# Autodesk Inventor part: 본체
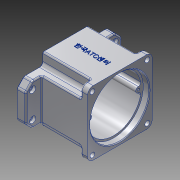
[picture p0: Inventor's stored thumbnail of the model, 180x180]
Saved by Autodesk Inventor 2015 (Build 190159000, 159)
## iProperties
Created: 2016-02
Part Number: 본체
Material: Aluminum 6061
Document SubType Name: Modeling
Designer: Administrator
Density: 2.7 g/cm^3
Appearance: Aluminum - Flat
Mass: 873.903 g
Surface Area: 763.799 cm^2
Volume: 323.668 cm^3
Author: Administrator
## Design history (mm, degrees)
sketch "Sketch1"
  geometry: L1 (60, 30)-(-60, 30); L2 (-70, 20)-(-70, -20); L3 (-60, -30)-(60, -30); L4 (70, -20)-(70, 20); L5 (70, 30)-(-70, -30); L6 (-70, 30)-(70, -30); L7 (60, 30)-(70, 20); L8 (60, -30)-(70, -20); L9 (-60, 30)-(-70, 20); L10 (-60, -30)-(-70, -20); 1 further point
  constraints: 20 end point, 8 point on line, 2 midpoint, 2 parallel, 1 horizontal, 1 perpendicular
  dimensions: "d0" = 140 distance of L6.end L5.end; "d1" = 60 distance of L5.end L6.start; "d2" = 10 distance of L1.start L5.start; "d3" = 10 distance of L4.end L5.start (= d2); "d4" = 10 distance of L3.end L6.end (= d2); "d5" = 10 distance of L4.start L6.end (= d4); "d6" = 10 distance of L1.end L6.start (= d2); "d7" = 10 distance of L2.start L6.start (= d6); "d8" = 10 distance of L3.start L5.end (= d2); "d9" = 10 distance of L2.end L5.end (= d8)
extrude "Extrusion1" new body sketch "Sketch1" distance "d10" = 13; taper "d11" = 0 deg
sketch "Sketch2"
  geometry: L1 (-19, -60)-(19, -60); L2 (19, -60)-(19, 60); L3 (19, 60)-(-19, 60); L4 (-19, 60)-(-19, -60); L5 (-19, -60)-(19, 60); L6 (19, -60)-(-19, 60); 5 further points
  constraints: 12 end point, 4 coincident, 2 midpoint, 2 parallel, 1 horizontal, 1 perpendicular
  dimensions: "d12" = 38 distance of L3.end L2.end; "d13" = 120 distance of L2.end L1.end
hole "Hole1" sketch "Sketch2" at (-19, -60), (19, -60), (19, 60), (-19, 60) diameter "d14" = 5; stored, may be unused: countersink angle "d18" = 90 deg, drill point angle "d20" = 0 deg; dims "d15" = 6.35, "d16" = 9, "d17" = 4, "d19" = 13
sketch "Sketch3"
  geometry: L1 (-47, -47)-(47, -47); L2 (47, -47)-(47, 47); L3 (47, 47)-(-47, 47); L4 (-47, 47)-(-47, -47); L5 (-47, -47)-(47, 47); L6 (47, -47)-(-47, 47); 1 further point
  constraints: 12 end point, 2 midpoint, 2 parallel, 1 horizontal, 1 perpendicular
  dimensions: "d21" = 94 distance of L3.end L2.end; "d22" = 94 distance of L2.end L1.end
extrude "Extrusion2" join sketch "Sketch3" distance "d23" = 67; taper "d24" = 0 deg
sketch "Sketch4"
  geometry: L1 (30, 33)-(47, 33); L2 (47, 33)-(47, 47); L3 (47, 47)-(30, 47); L4 (30, 47)-(30, 33); L5 (30, 33)-(47, 47); L6 (47, 33)-(30, 47); L7 (47, 47)-(47, -47) reference; L8 (30, 47)-(47, 47) reference; 2 further points
  constraints: 12 end point, 2 midpoint, 2 parallel, 1 collinear, 1 horizontal, 1 perpendicular
  dimensions: "d25" = 33 vertical distance of point (0, 0) L1.end; "d26" = 30 distance from line of L4 point (0, 0)
extrude "Extrusion3" cut sketch "Sketch4" distance "d27" = 57; taper "d28" = 0 deg
mirror "Mirror1"
mirror "Mirror2"
sketch "Sketch5"
  geometry: L1 (40, 40)-(-40, 40); L2 (-40, 40)-(-40, -40); L3 (-40, -40)-(40, -40); L4 (40, -40)-(40, 40); L5 (40, 40)-(-40, -40); L6 (-40, 40)-(40, -40); C1 r 3.5 at (-40, -40); C2 r 3.5 at (-40, 40); C3 r 3.5 at (40, 40); C4 r 3.5 at (40, -40); 1 further point
  constraints: 12 end point, 4 centre point, 4 coincident, 2 midpoint, 2 parallel, 1 horizontal, 1 perpendicular
  dimensions: "d29" = 80 distance of L3.end L2.end; "d30" = 80 distance of L2.end L1.end; "d31" = 7 diameter of C1; "d32" = 7 diameter of C2; "d33" = 7 diameter of C3; "d34" = 7 diameter of C4
extrude "Extrusion4" cut sketch "Sketch5" distance "d35" = 10; taper "d36" = 0 deg
sketch "Sketch6"
  geometry: L1 (30, -33)-(47, -33) reference; L2 (47, 33)-(47, -33) reference; L3 (47, 33)-(30, 33) reference; L4 (30, 33)-(30, -33) reference; L5 (-47, -33)-(-30, -33) reference; L6 (-30, -33)-(-30, 33) reference; L7 (-30, 33)-(-47, 33) reference; L8 (-47, -33)-(-47, 33) reference; 1 further point
extrude "Extrusion5" join sketch "Sketch6" distance "d37" = 13; taper "d38" = 0 deg
sketch "Sketch7"
  geometry: C1 r 28 at (11, 0); 1 further point
  constraints: 1 centre point, 1 horizontal alignment
  dimensions: "d39" = 56 diameter of C1; "d40" = 11 distance of point (0, 0) C1.centre
extrude "Extrusion6" join sketch "Sketch7" distance "d41" = 7; taper "d42" = -10 deg
sketch "Sketch8"
  geometry: 2 further points
  constraints: 1 coincident
hole "Hole2" sketch "Sketch8" at (0, 0) diameter "d43" = 80; stored, may be unused: countersink angle "d47" = 90 deg, drill point angle "d49" = 0 deg; dims "d44" = 6.35, "d45" = 86, "d46" = 9, "d48" = 71
sketch "Sketch9"
  geometry: A1 r 21 centre (-11, 0) between (7.984, 8.978) and (7.984, -8.978); A2 r 15 centre (20, 0) between (7.984, -8.978) and (7.984, 8.978); 1 further point
  constraints: 4 point on circle, 2 centre point, 2 horizontal alignment
  dimensions: "d50" = 21 radius of A1; "d51" = 15 radius of A2; "d52" = 11 distance of point (0, 0) A1.centre; "d53" = 20 distance of point (0, 0) A2.centre
extrude "Extrusion7" join sketch "Sketch9" distance "d54" = 7; taper "d55" = 0 deg
hole "Hole3" diameter "d58" = 25; stored, may be unused: countersink angle "d62" = 90 deg, drill point angle "d64" = 0 deg; dims "d59" = 6.35, "d60" = 35, "d61" = 10, "d63" = 15, "d93" = 10, "d94" = 10
hole "Hole4" diameter "d67" = 19; stored, may be unused: countersink angle "d71" = 90 deg, drill point angle "d73" = 0 deg; dims "d65" = 10, "d66" = 10, "d68" = 6.35, "d69" = 22, "d70" = 7, "d72" = 8
hole "Hole5" diameter "d76" = 32; stored, may be unused: countersink angle "d80" = 90 deg, drill point angle "d82" = 0 deg; dims "d77" = 6.35, "d78" = 22, "d79" = 7, "d81" = 8, "d95" = 10, "d96" = 10
chamfer "Chamfer1" distance "d83" = 1; stored, may be unused: second distance "d84" = 2, angle "d85" = 45 deg
fillet "Fillet2" dims "d87" = 2
sketch "Sketch12" dims "d98" = 36
  geometry: A1 r 40 centre (0, 0) between (-8.214, -39.148) and (8.214, -39.148) reference; A2 r 4 centre (0, -36) between (3.997, -35.852) and (-3.997, -35.852); A3 r 3.5 centre (-7.495, -35.722) between (-8.214, -39.148) and (-3.997, -35.852); A4 r 3.5 centre (7.495, -35.722) between (3.997, -35.852) and (8.214, -39.148); A5 r 40 centre (0, 0) between (-8.214, -39.148) and (8.214, -39.148); 2 further points
  constraints: 10 point on circle, 4 centre point, 4 tangent, 2 coincident, 2 vertical alignment, 1 equal radius, 2 other
  dimensions: "d97" = 4 radius of A2; "d99" = 3.5 radius of A3; "d100" = 3.5 radius of A4 (derived)
extrude "Extrusion8" join sketch "Sketch12" distance "d101" = 62; taper "d102" = 0 deg
mirror "Mirror3"
sketch "Sketch13"
  geometry: A1 r 4 centre (0, -36) between (3.997, -35.852) and (-3.997, -35.852) reference; A2 r 4 centre (0, 36) between (-3.997, 35.852) and (3.997, 35.852) reference; 3 further points
  constraints: 2 coincident
hole "Hole6" sketch "Sketch13" at (0, -36), (0, 36) diameter "d103" = 3.242; stored, may be unused: countersink angle "d107" = 90 deg, drill point angle "d109" = 118 deg; dims "d104" = 7, "d105" = 22, "d106" = 7, "d108" = 9
fillet "Fillet3" dims "d110" = 5
fillet "Fillet4" dims "d111" = 8
fillet "Fillet5" dims "d112" = 2
sketch "Sketch14"
  geometry: L1 (-80, 8)-(-80, 70) reference; L2 (0, 78)-(0, 0) reference; 3 further points
  constraints: 1 horizontal alignment, 1 midpoint, 1 other
  dimensions: "d113" = 40 distance from line of L2 point (-40, 39)
emboss "Emboss1" sketch "Sketch14" dims "d0" = 140, "d1" = 60, "d2" = 10, "d3" = 10 (= d2), "d4" = 10 (= d2), "d5" = 10 (= d4), "d6" = 10 (= d2), "d7" = 10 (= d6), "d8" = 10 (= d2), "d9" = 10 (= d8), "d114" = 0.5, "d115" = 0
sketch "Sketch17"
  geometry: L1 (30, 38)-(30, 57.929) reference; L2 (28.536, 61.464)-(21.464, 68.536) reference; L3 (17.929, 70)-(-17.929, 70) reference; L4 (-21.464, 68.536)-(-28.536, 61.464) reference; L5 (-30, 57.929)-(-30, 38) reference; L6 (-35, 33)-(-45, 33) reference; L7 (-47, 31)-(-47, -31) reference; L8 (-45, -33)-(-35, -33) reference; L9 (-30, -38)-(-30, -57.929) reference; L10 (-28.536, -61.464)-(-21.464, -68.536) reference; L11 (-17.929, -70)-(17.929, -70) reference; L12 (21.464, -68.536)-(28.536, -61.464) reference; L13 (30, -57.929)-(30, -38) reference; L14 (35, -33)-(45, -33) reference; L15 (47, -31)-(47, 31) reference; L16 (45, 33)-(35, 33) reference; L17 (46, 31)-(46, -31); L18 (45, -32)-(35, -32); L19 (29, -38)-(29, -57.929); L20 (27.828, -60.757)-(20.757, -67.828); L21 (17.929, -69)-(-17.929, -69); L22 (-20.757, -67.828)-(-27.828, -60.757); L23 (-29, -57.929)-(-29, -38); L24 (-35, -32)-(-45, -32); L25 (-46, -31)-(-46, 31); L26 (-45, 32)-(-35, 32); L27 (-29, 38)-(-29, 57.929); L28 (-27.828, 60.757)-(-20.757, 67.828); L29 (-17.929, 69)-(17.929, 69); L30 (20.757, 67.828)-(27.828, 60.757); L31 (29, 57.929)-(29, 38); L32 (35, 32)-(45, 32); C1 r 28 at (11, 0) reference; A1 r 5 centre (25, 57.929) between (30, 57.929) and (28.536, 61.464) reference; A2 r 5 centre (17.929, 65) between (21.464, 68.536) and (17.929, 70) reference; A3 r 5 centre (-17.929, 65) between (-17.929, 70) and (-21.464, 68.536) reference; A4 r 5 centre (-25, 57.929) between (-28.536, 61.464) and (-30, 57.929) reference; A5 r 5 centre (-35, 38) between (-35, 33) and (-30, 38) reference; A6 r 2 centre (-45, 31) between (-45, 33) and (-47, 31) reference; A7 r 2 centre (-45, -31) between (-47, -31) and (-45, -33) reference; A8 r 5 centre (-35, -38) between (-30, -38) and (-35, -33) reference; A9 r 5 centre (-25, -57.929) between (-30, -57.929) and (-28.536, -61.464) reference; A10 r 5 centre (-17.929, -65) between (-21.464, -68.536) and (-17.929, -70) reference; A11 r 5 centre (17.929, -65) between (17.929, -70) and (21.464, -68.536) reference; A12 r 5 centre (25, -57.929) between (28.536, -61.464) and (30, -57.929) reference; A13 r 5 centre (35, -38) between (35, -33) and (30, -38) reference; A14 r 2 centre (45, -31) between (45, -33) and (47, -31) reference; A15 r 2 centre (45, 31) between (47, 31) and (45, 33) reference; A16 r 5 centre (35, 38) between (30, 38) and (35, 33) reference; A17 r 1 centre (45, -31) between (45, -32) and (46, -31); A18 r 6 centre (35, -38) between (35, -32) and (29, -38); A19 r 4 centre (25, -57.929) between (27.828, -60.757) and (29, -57.929); A20 r 4 centre (17.929, -65) between (17.929, -69) and (20.757, -67.828); A21 r 4 centre (-17.929, -65) between (-20.757, -67.828) and (-17.929, -69); A22 r 4 centre (-25, -57.929) between (-29, -57.929) and (-27.828, -60.757); A23 r 6 centre (-35, -38) between (-29, -38) and (-35, -32); A24 r 1 centre (-45, -31) between (-46, -31) and (-45, -32); A25 r 1 centre (-45, 31) between (-45, 32) and (-46, 31); A26 r 6 centre (-35, 38) between (-35, 32) and (-29, 38); A27 r 4 centre (-25, 57.929) between (-27.828, 60.757) and (-29, 57.929); A28 r 4 centre (-17.929, 65) between (-17.929, 69) and (-20.757, 67.828); A29 r 4 centre (17.929, 65) between (20.757, 67.828) and (17.929, 69); A30 r 4 centre (25, 57.929) between (29, 57.929) and (27.828, 60.757); A31 r 6 centre (35, 38) between (29, 38) and (35, 32); A32 r 1 centre (45, 31) between (46, 31) and (45, 32); 1 further point
  constraints: 32 end point, 32 point on circle, 16 centre point, 31 other
  dimensions: "d116" = 1 distance between parallel lines of L15 L17
extrude "Extrusion9" cut sketch "Sketch17" distance "d117" = 1; taper "d118" = 0 deg
fillet "Fillet6" dims "d119" = 0.3
fillet "Fillet7" dims "d120" = 3
body "Solid1"
node "Projected Loop1"
node "Projected Loop2"
other parameters: "d91" = 3.5
